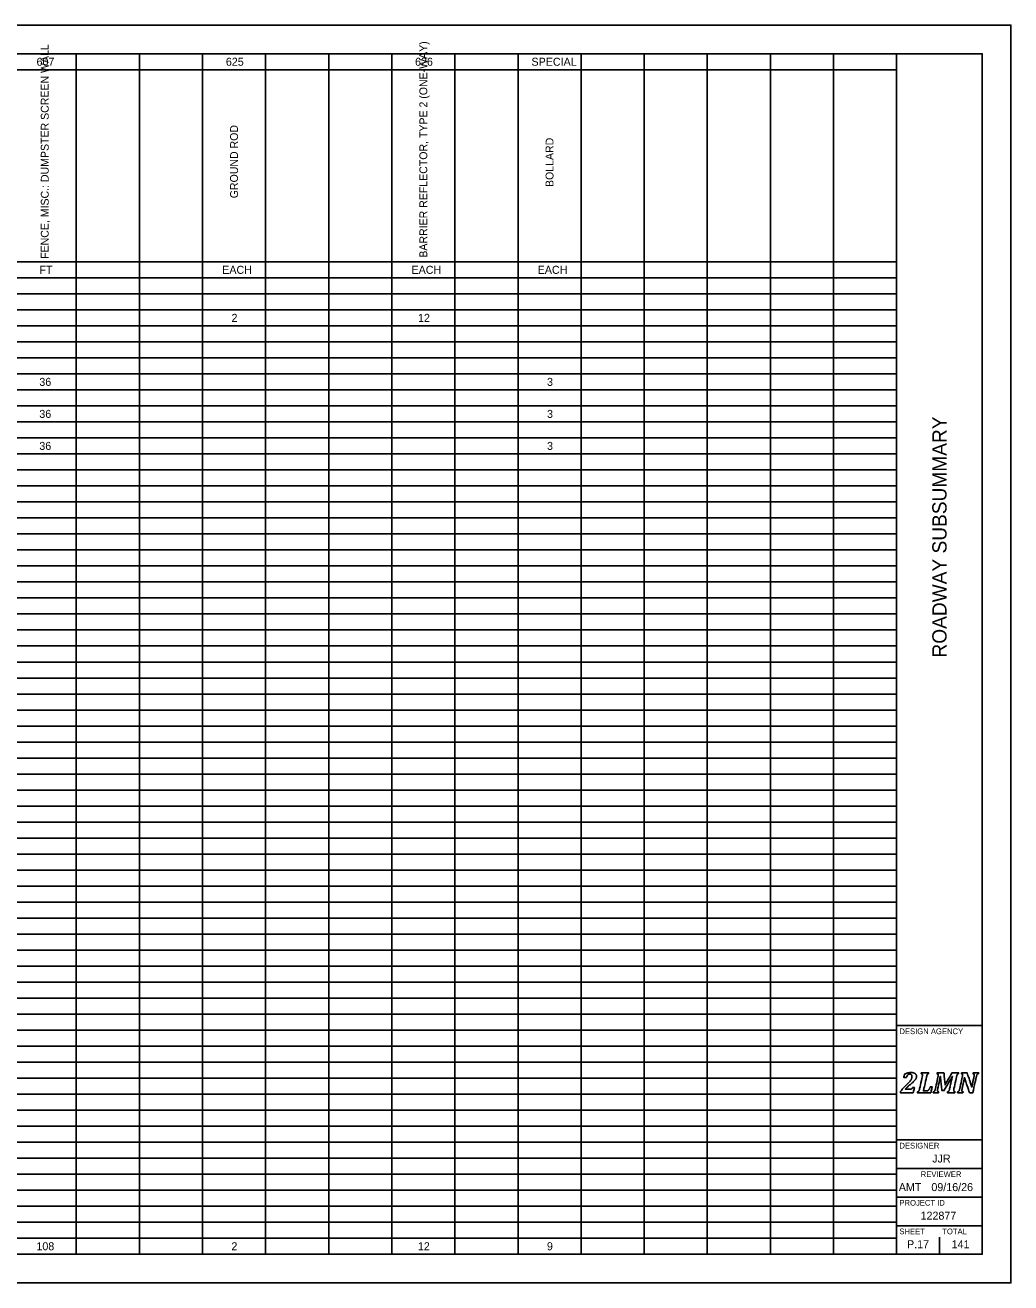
# Model space of a CAD drawing. Extents: x 0 to 34, y 0 to 22.
# Drawn here: x 16.75 to 34, y 0 to 22 of the extents above; entities that cross this region are included whole.
import ezdxf

# ---------------------------------------------------------------- set-up
doc = ezdxf.new("R2010")
doc.units = 0
for name, color, linetype in [('SH_Border', 7, 'Continuous'), ('SH_Cut_Line', 7, 'Continuous'), ('SH_Data', 7, 'Continuous'), ('SH_Text', 7, 'Continuous')]:
    doc.layers.add(name, color=color, linetype=linetype)

msp = doc.modelspace()

# ---------------------------------------------------------------- linework, layer by layer
at = {"layer": 'SH_Border'}
for p, q in [((32, 0.5), (32, 21.5)), ((32, 4.5), (33.5, 4.5)), ((32, 2.5), (33.5, 2.5)), ((32, 2), (33.5, 2)), ((32, 1.5), (33.5, 1.5)), ((32, 1), (33.5, 1))]:
    msp.add_line(p, q, dxfattribs=at)
msp.add_lwpolyline([(1.5, 21.5), (33.5, 21.5), (33.5, 0.5), (1.5, 0.5)], close=True, dxfattribs=at)
at = {"layer": 'SH_Cut_Line'}
msp.add_lwpolyline([(0, 0), (34, 0), (34, 22), (0, 22)], close=True, dxfattribs=at)
at = {"layer": 'SH_Data'}
for p, q in [((32.75, 3.5), (32.75, 3.5)), ((32.375, 0.675), (32.375, 0.675)), ((32.75, 0.5), (32.75, 0.8))]:
    msp.add_line(p, q, dxfattribs=at)
for points in [[(32.237, 3.388), (32.246, 3.388), (32.253, 3.389), (32.258, 3.39), (32.263, 3.392), (32.267, 3.394), (32.27, 3.397), (32.273, 3.401), (32.277, 3.408), (32.281, 3.417), (32.281, 3.417), (32.312, 3.417), (32.312, 3.417), (32.312, 3.417), (32.29, 3.326), (32.29, 3.326), (32.29, 3.326), (32.066, 3.326), (32.066, 3.326), (32.066, 3.326), (32.069, 3.343), (32.069, 3.343), (32.078, 3.358), (32.091, 3.375), (32.106, 3.394), (32.122, 3.412), (32.144, 3.435), (32.172, 3.462), (32.197, 3.486), (32.217, 3.506), (32.23, 3.521), (32.243, 3.537), (32.253, 3.551), (32.259, 3.566), (32.266, 3.58), (32.269, 3.595), (32.269, 3.61), (32.269, 3.622), (32.266, 3.632), (32.26, 3.64), (32.253, 3.647), (32.245, 3.65), (32.234, 3.65), (32.22, 3.65), (32.208, 3.646), (32.198, 3.636), (32.188, 3.627), (32.18, 3.613), (32.172, 3.593), (32.172, 3.593), (32.126, 3.593), (32.126, 3.593), (32.126, 3.593), (32.14, 3.654), (32.14, 3.654), (32.166, 3.663), (32.188, 3.669), (32.205, 3.673), (32.223, 3.676), (32.24, 3.678), (32.258, 3.678), (32.278, 3.678), (32.295, 3.675), (32.309, 3.669), (32.322, 3.664), (32.332, 3.656), (32.339, 3.646), (32.345, 3.637), (32.348, 3.626), (32.348, 3.613), (32.348, 3.602), (32.346, 3.591), (32.342, 3.581), (32.339, 3.571), (32.333, 3.56), (32.324, 3.549), (32.315, 3.539), (32.304, 3.526), (32.289, 3.513), (32.275, 3.499), (32.254, 3.482), (32.228, 3.46), (32.216, 3.45), (32.202, 3.438), (32.188, 3.425), (32.174, 3.412), (32.162, 3.4), (32.154, 3.391), (32.154, 3.391), (32.153, 3.388), (32.153, 3.388), (32.153, 3.388), (32.237, 3.388), (32.237, 3.388)], [(32.237, 3.388), (32.237, 3.388), (32.153, 3.388), (32.153, 3.388), (32.153, 3.388), (32.154, 3.391), (32.154, 3.391), (32.162, 3.4), (32.174, 3.412), (32.188, 3.425), (32.202, 3.438), (32.216, 3.45), (32.228, 3.46), (32.254, 3.482), (32.275, 3.499), (32.289, 3.513), (32.304, 3.526), (32.315, 3.539), (32.324, 3.549), (32.333, 3.56), (32.339, 3.571), (32.342, 3.581), (32.346, 3.591), (32.348, 3.602), (32.348, 3.613), (32.348, 3.626), (32.345, 3.637), (32.339, 3.646), (32.332, 3.656), (32.322, 3.664), (32.309, 3.669), (32.295, 3.675), (32.278, 3.678), (32.258, 3.678), (32.24, 3.678), (32.223, 3.676), (32.205, 3.673), (32.188, 3.669), (32.166, 3.663), (32.14, 3.654), (32.14, 3.654), (32.126, 3.593), (32.126, 3.593), (32.126, 3.593), (32.172, 3.593), (32.172, 3.593), (32.18, 3.613), (32.188, 3.627), (32.198, 3.636), (32.208, 3.646), (32.22, 3.65), (32.234, 3.65), (32.245, 3.65), (32.253, 3.647), (32.26, 3.64), (32.266, 3.632), (32.269, 3.622), (32.269, 3.61), (32.269, 3.595), (32.266, 3.58), (32.259, 3.566), (32.253, 3.551), (32.243, 3.537), (32.23, 3.521), (32.217, 3.506), (32.197, 3.486), (32.172, 3.462), (32.144, 3.435), (32.122, 3.412), (32.106, 3.394), (32.091, 3.375), (32.078, 3.358), (32.069, 3.343), (32.069, 3.343), (32.066, 3.326), (32.066, 3.326), (32.066, 3.326), (32.29, 3.326), (32.29, 3.326), (32.29, 3.326), (32.312, 3.417), (32.312, 3.417), (32.312, 3.417), (32.281, 3.417), (32.281, 3.417), (32.277, 3.408), (32.273, 3.401), (32.27, 3.397), (32.267, 3.394), (32.263, 3.392), (32.258, 3.39), (32.253, 3.389), (32.246, 3.388), (32.237, 3.388)], [(32.518, 3.356), (32.527, 3.356), (32.533, 3.357), (32.538, 3.358), (32.542, 3.36), (32.546, 3.362), (32.55, 3.365), (32.554, 3.368), (32.558, 3.372), (32.562, 3.377), (32.567, 3.382), (32.571, 3.388), (32.576, 3.397), (32.58, 3.405), (32.585, 3.415), (32.589, 3.427), (32.589, 3.427), (32.624, 3.427), (32.624, 3.427), (32.624, 3.427), (32.598, 3.326), (32.598, 3.326), (32.598, 3.326), (32.365, 3.326), (32.365, 3.326), (32.365, 3.326), (32.369, 3.343), (32.369, 3.343), (32.376, 3.345), (32.381, 3.348), (32.385, 3.351), (32.389, 3.355), (32.392, 3.36), (32.395, 3.366), (32.398, 3.373), (32.4, 3.382), (32.403, 3.395), (32.403, 3.395), (32.449, 3.605), (32.449, 3.605), (32.452, 3.615), (32.453, 3.625), (32.453, 3.635), (32.453, 3.642), (32.451, 3.647), (32.448, 3.651), (32.444, 3.654), (32.439, 3.656), (32.432, 3.657), (32.432, 3.657), (32.435, 3.674), (32.435, 3.674), (32.435, 3.674), (32.563, 3.674), (32.563, 3.674), (32.563, 3.674), (32.559, 3.657), (32.559, 3.657), (32.552, 3.655), (32.547, 3.652), (32.543, 3.649), (32.539, 3.645), (32.536, 3.64), (32.533, 3.634), (32.531, 3.627), (32.528, 3.618), (32.525, 3.605), (32.525, 3.605), (32.47, 3.356), (32.47, 3.356), (32.47, 3.356), (32.518, 3.356), (32.518, 3.356)], [(32.518, 3.356), (32.518, 3.356), (32.47, 3.356), (32.47, 3.356), (32.47, 3.356), (32.525, 3.605), (32.525, 3.605), (32.528, 3.618), (32.531, 3.627), (32.533, 3.634), (32.536, 3.64), (32.539, 3.645), (32.543, 3.649), (32.547, 3.652), (32.552, 3.655), (32.559, 3.657), (32.559, 3.657), (32.563, 3.674), (32.563, 3.674), (32.563, 3.674), (32.435, 3.674), (32.435, 3.674), (32.435, 3.674), (32.432, 3.657), (32.432, 3.657), (32.439, 3.656), (32.444, 3.654), (32.448, 3.651), (32.451, 3.647), (32.453, 3.642), (32.453, 3.635), (32.453, 3.625), (32.452, 3.615), (32.449, 3.605), (32.449, 3.605), (32.403, 3.395), (32.403, 3.395), (32.4, 3.382), (32.398, 3.373), (32.395, 3.366), (32.392, 3.36), (32.389, 3.355), (32.385, 3.351), (32.381, 3.348), (32.376, 3.345), (32.369, 3.343), (32.369, 3.343), (32.365, 3.326), (32.365, 3.326), (32.365, 3.326), (32.598, 3.326), (32.598, 3.326), (32.598, 3.326), (32.624, 3.427), (32.624, 3.427), (32.624, 3.427), (32.589, 3.427), (32.589, 3.427), (32.585, 3.415), (32.58, 3.405), (32.576, 3.397), (32.571, 3.388), (32.567, 3.382), (32.562, 3.377), (32.558, 3.372), (32.554, 3.368), (32.55, 3.365), (32.546, 3.362), (32.542, 3.36), (32.538, 3.358), (32.533, 3.357), (32.527, 3.356), (32.518, 3.356)], [(32.829, 3.674), (32.829, 3.674), (32.849, 3.461), (32.849, 3.461), (32.849, 3.461), (32.969, 3.674), (32.969, 3.674), (32.969, 3.674), (33.087, 3.674), (33.087, 3.674), (33.087, 3.674), (33.084, 3.657), (33.084, 3.657), (33.077, 3.655), (33.071, 3.652), (33.067, 3.649), (33.064, 3.645), (33.06, 3.64), (33.058, 3.634), (33.055, 3.627), (33.052, 3.618), (33.05, 3.605), (33.05, 3.605), (33.003, 3.395), (33.003, 3.395), (33.002, 3.39), (33.002, 3.387), (33.001, 3.384), (33.001, 3.382), (33.001, 3.379), (33, 3.376), (33, 3.373), (33, 3.369), (33, 3.365), (33, 3.358), (33.002, 3.353), (33.005, 3.349), (33.008, 3.346), (33.014, 3.344), (33.021, 3.343), (33.021, 3.343), (33.018, 3.326), (33.018, 3.326), (33.018, 3.326), (32.89, 3.326), (32.89, 3.326), (32.89, 3.326), (32.893, 3.343), (32.893, 3.343), (32.9, 3.345), (32.906, 3.348), (32.91, 3.351), (32.914, 3.355), (32.917, 3.36), (32.919, 3.366), (32.922, 3.373), (32.925, 3.382), (32.928, 3.395), (32.928, 3.395), (32.951, 3.502), (32.951, 3.502), (32.954, 3.513), (32.957, 3.529), (32.962, 3.548), (32.967, 3.568), (32.972, 3.588), (32.978, 3.609), (32.978, 3.609), (32.973, 3.609), (32.973, 3.609), (32.965, 3.594), (32.957, 3.579), (32.948, 3.563), (32.948, 3.563), (32.833, 3.364), (32.833, 3.364), (32.833, 3.364), (32.792, 3.364), (32.792, 3.364), (32.792, 3.364), (32.775, 3.518), (32.775, 3.518), (32.773, 3.537), (32.772, 3.554), (32.77, 3.569), (32.769, 3.583), (32.768, 3.597), (32.768, 3.611), (32.768, 3.611), (32.764, 3.611), (32.764, 3.611), (32.761, 3.596), (32.758, 3.578), (32.755, 3.558), (32.751, 3.538), (32.747, 3.521), (32.744, 3.507), (32.744, 3.507), (32.72, 3.395), (32.72, 3.395), (32.719, 3.39), (32.718, 3.387), (32.718, 3.384), (32.717, 3.382), (32.717, 3.379), (32.717, 3.376), (32.717, 3.373), (32.716, 3.369), (32.716, 3.365), (32.716, 3.358), (32.718, 3.353), (32.721, 3.349), (32.725, 3.346), (32.73, 3.344), (32.738, 3.343), (32.738, 3.343), (32.734, 3.326), (32.734, 3.326), (32.734, 3.326), (32.641, 3.326), (32.641, 3.326), (32.641, 3.326), (32.644, 3.343), (32.644, 3.343), (32.651, 3.345), (32.657, 3.348), (32.661, 3.351), (32.665, 3.355), (32.668, 3.36), (32.67, 3.366), (32.673, 3.373), (32.676, 3.382), (32.679, 3.395), (32.679, 3.395), (32.725, 3.605), (32.725, 3.605), (32.727, 3.615), (32.728, 3.625), (32.728, 3.635), (32.728, 3.642), (32.727, 3.647), (32.723, 3.651), (32.72, 3.654), (32.715, 3.656), (32.707, 3.657), (32.707, 3.657), (32.711, 3.674), (32.711, 3.674), (32.711, 3.674), (32.829, 3.674), (32.829, 3.674)], [(32.829, 3.674), (32.829, 3.674), (32.711, 3.674), (32.711, 3.674), (32.711, 3.674), (32.707, 3.657), (32.707, 3.657), (32.715, 3.656), (32.72, 3.654), (32.723, 3.651), (32.727, 3.647), (32.728, 3.642), (32.728, 3.635), (32.728, 3.625), (32.727, 3.615), (32.725, 3.605), (32.725, 3.605), (32.679, 3.395), (32.679, 3.395), (32.676, 3.382), (32.673, 3.373), (32.67, 3.366), (32.668, 3.36), (32.665, 3.355), (32.661, 3.351), (32.657, 3.348), (32.651, 3.345), (32.644, 3.343), (32.644, 3.343), (32.641, 3.326), (32.641, 3.326), (32.641, 3.326), (32.734, 3.326), (32.734, 3.326), (32.734, 3.326), (32.738, 3.343), (32.738, 3.343), (32.73, 3.344), (32.725, 3.346), (32.721, 3.349), (32.718, 3.353), (32.716, 3.358), (32.716, 3.365), (32.716, 3.369), (32.717, 3.373), (32.717, 3.376), (32.717, 3.379), (32.717, 3.382), (32.718, 3.384), (32.718, 3.387), (32.719, 3.39), (32.72, 3.395), (32.72, 3.395), (32.744, 3.507), (32.744, 3.507), (32.747, 3.521), (32.751, 3.538), (32.755, 3.558), (32.758, 3.578), (32.761, 3.596), (32.764, 3.611), (32.764, 3.611), (32.768, 3.611), (32.768, 3.611), (32.768, 3.597), (32.769, 3.583), (32.77, 3.569), (32.772, 3.554), (32.773, 3.537), (32.775, 3.518), (32.775, 3.518), (32.792, 3.364), (32.792, 3.364), (32.792, 3.364), (32.833, 3.364), (32.833, 3.364), (32.833, 3.364), (32.948, 3.563), (32.948, 3.563), (32.957, 3.579), (32.965, 3.594), (32.973, 3.609), (32.973, 3.609), (32.978, 3.609), (32.978, 3.609), (32.972, 3.588), (32.967, 3.568), (32.962, 3.548), (32.957, 3.529), (32.954, 3.513), (32.951, 3.502), (32.951, 3.502), (32.928, 3.395), (32.928, 3.395), (32.925, 3.382), (32.922, 3.373), (32.919, 3.366), (32.917, 3.36), (32.914, 3.355), (32.91, 3.351), (32.906, 3.348), (32.9, 3.345), (32.893, 3.343), (32.893, 3.343), (32.89, 3.326), (32.89, 3.326), (32.89, 3.326), (33.018, 3.326), (33.018, 3.326), (33.018, 3.326), (33.021, 3.343), (33.021, 3.343), (33.014, 3.344), (33.008, 3.346), (33.005, 3.349), (33.002, 3.353), (33, 3.358), (33, 3.365), (33, 3.369), (33, 3.373), (33, 3.376), (33.001, 3.379), (33.001, 3.382), (33.001, 3.384), (33.002, 3.387), (33.002, 3.39), (33.003, 3.395), (33.003, 3.395), (33.05, 3.605), (33.05, 3.605), (33.052, 3.618), (33.055, 3.627), (33.058, 3.634), (33.06, 3.64), (33.064, 3.645), (33.067, 3.649), (33.071, 3.652), (33.077, 3.655), (33.084, 3.657), (33.084, 3.657), (33.087, 3.674), (33.087, 3.674), (33.087, 3.674), (32.969, 3.674), (32.969, 3.674), (32.969, 3.674), (32.849, 3.461), (32.849, 3.461), (32.849, 3.461), (32.829, 3.674), (32.829, 3.674)], [(33.137, 3.674), (33.137, 3.674), (33.234, 3.674), (33.234, 3.674), (33.234, 3.674), (33.283, 3.53), (33.283, 3.53), (33.296, 3.49), (33.307, 3.456), (33.315, 3.426), (33.315, 3.426), (33.318, 3.426), (33.318, 3.426), (33.323, 3.455), (33.329, 3.488), (33.337, 3.523), (33.337, 3.523), (33.355, 3.605), (33.355, 3.605), (33.357, 3.615), (33.358, 3.625), (33.358, 3.635), (33.358, 3.642), (33.357, 3.647), (33.353, 3.651), (33.35, 3.654), (33.345, 3.656), (33.337, 3.657), (33.337, 3.657), (33.341, 3.674), (33.341, 3.674), (33.341, 3.674), (33.434, 3.674), (33.434, 3.674), (33.434, 3.674), (33.431, 3.657), (33.431, 3.657), (33.424, 3.655), (33.418, 3.652), (33.414, 3.649), (33.41, 3.645), (33.407, 3.64), (33.405, 3.634), (33.402, 3.627), (33.399, 3.618), (33.396, 3.605), (33.396, 3.605), (33.335, 3.326), (33.335, 3.326), (33.335, 3.326), (33.277, 3.326), (33.277, 3.326), (33.277, 3.326), (33.216, 3.504), (33.216, 3.504), (33.211, 3.518), (33.207, 3.531), (33.204, 3.543), (33.2, 3.556), (33.195, 3.571), (33.19, 3.59), (33.19, 3.59), (33.186, 3.59), (33.186, 3.59), (33.185, 3.579), (33.182, 3.563), (33.179, 3.543), (33.175, 3.523), (33.17, 3.501), (33.165, 3.478), (33.165, 3.478), (33.147, 3.395), (33.147, 3.395), (33.146, 3.39), (33.145, 3.387), (33.145, 3.384), (33.144, 3.382), (33.144, 3.379), (33.144, 3.376), (33.143, 3.373), (33.143, 3.369), (33.143, 3.365), (33.143, 3.358), (33.145, 3.353), (33.148, 3.349), (33.152, 3.346), (33.157, 3.344), (33.164, 3.343), (33.164, 3.343), (33.161, 3.326), (33.161, 3.326), (33.161, 3.326), (33.067, 3.326), (33.067, 3.326), (33.067, 3.326), (33.071, 3.343), (33.071, 3.343), (33.078, 3.345), (33.083, 3.348), (33.087, 3.351), (33.091, 3.355), (33.094, 3.36), (33.097, 3.366), (33.1, 3.373), (33.102, 3.382), (33.105, 3.395), (33.105, 3.395), (33.151, 3.605), (33.151, 3.605), (33.154, 3.615), (33.155, 3.625), (33.155, 3.635), (33.155, 3.642), (33.153, 3.647), (33.15, 3.651), (33.146, 3.654), (33.141, 3.656), (33.134, 3.657), (33.134, 3.657), (33.137, 3.674), (33.137, 3.674)], [(33.137, 3.674), (33.137, 3.674), (33.134, 3.657), (33.134, 3.657), (33.141, 3.656), (33.146, 3.654), (33.15, 3.651), (33.153, 3.647), (33.155, 3.642), (33.155, 3.635), (33.155, 3.625), (33.154, 3.615), (33.151, 3.605), (33.151, 3.605), (33.105, 3.395), (33.105, 3.395), (33.102, 3.382), (33.1, 3.373), (33.097, 3.366), (33.094, 3.36), (33.091, 3.355), (33.087, 3.351), (33.083, 3.348), (33.078, 3.345), (33.071, 3.343), (33.071, 3.343), (33.067, 3.326), (33.067, 3.326), (33.067, 3.326), (33.161, 3.326), (33.161, 3.326), (33.161, 3.326), (33.164, 3.343), (33.164, 3.343), (33.157, 3.344), (33.152, 3.346), (33.148, 3.349), (33.145, 3.353), (33.143, 3.358), (33.143, 3.365), (33.143, 3.369), (33.143, 3.373), (33.144, 3.376), (33.144, 3.379), (33.144, 3.382), (33.145, 3.384), (33.145, 3.387), (33.146, 3.39), (33.147, 3.395), (33.147, 3.395), (33.165, 3.478), (33.165, 3.478), (33.17, 3.501), (33.175, 3.523), (33.179, 3.543), (33.182, 3.563), (33.185, 3.579), (33.186, 3.59), (33.186, 3.59), (33.19, 3.59), (33.19, 3.59), (33.195, 3.571), (33.2, 3.556), (33.204, 3.543), (33.207, 3.531), (33.211, 3.518), (33.216, 3.504), (33.216, 3.504), (33.277, 3.326), (33.277, 3.326), (33.277, 3.326), (33.335, 3.326), (33.335, 3.326), (33.335, 3.326), (33.396, 3.605), (33.396, 3.605), (33.399, 3.618), (33.402, 3.627), (33.405, 3.634), (33.407, 3.64), (33.41, 3.645), (33.414, 3.649), (33.418, 3.652), (33.424, 3.655), (33.431, 3.657), (33.431, 3.657), (33.434, 3.674), (33.434, 3.674), (33.434, 3.674), (33.341, 3.674), (33.341, 3.674), (33.341, 3.674), (33.337, 3.657), (33.337, 3.657), (33.345, 3.656), (33.35, 3.654), (33.353, 3.651), (33.357, 3.647), (33.358, 3.642), (33.358, 3.635), (33.358, 3.625), (33.357, 3.615), (33.355, 3.605), (33.355, 3.605), (33.337, 3.523), (33.337, 3.523), (33.329, 3.488), (33.323, 3.455), (33.318, 3.426), (33.318, 3.426), (33.315, 3.426), (33.315, 3.426), (33.307, 3.456), (33.296, 3.49), (33.283, 3.53), (33.283, 3.53), (33.234, 3.674), (33.234, 3.674), (33.234, 3.674), (33.137, 3.674), (33.137, 3.674)]]:
    msp.add_open_spline(points, degree=3, dxfattribs=at)
at = {"layer": 'SH_Text'}
for p, q in [((1.5, 21.5), (32, 21.5)), ((17.643, 21.5), (17.643, 0.5)), ((18.748, 21.5), (18.748, 0.5)), ((19.852, 21.5), (19.852, 0.5)), ((20.956, 21.5), (20.956, 0.5)), ((22.061, 21.5), (22.061, 0.5)), ((23.165, 21.5), (23.165, 0.5)), ((24.269, 21.5), (24.269, 0.5)), ((25.374, 21.5), (25.374, 0.5)), ((26.478, 21.5), (26.478, 0.5)), ((27.583, 21.5), (27.583, 0.5)), ((28.687, 21.5), (28.687, 0.5)), ((29.791, 21.5), (29.791, 0.5)), ((30.896, 21.5), (30.896, 0.5)), ((32, 21.5), (32, 0.5)), ((9.913, 21.22), (32, 21.22)), ((9.913, 17.86), (32, 17.86)), ((1.5, 17.58), (32, 17.58)), ((1.5, 17.3), (32, 17.3)), ((1.5, 17.02), (32, 17.02)), ((1.5, 16.74), (32, 16.74)), ((1.5, 16.46), (32, 16.46)), ((1.5, 16.18), (32, 16.18)), ((1.5, 15.9), (32, 15.9)), ((1.5, 15.62), (32, 15.62)), ((1.5, 15.34), (32, 15.34)), ((1.5, 15.06), (32, 15.06)), ((1.5, 14.78), (32, 14.78)), ((1.5, 14.5), (32, 14.5)), ((1.5, 14.22), (32, 14.22)), ((1.5, 13.94), (32, 13.94)), ((1.5, 13.66), (32, 13.66)), ((1.5, 13.38), (32, 13.38)), ((1.5, 13.1), (32, 13.1)), ((1.5, 12.82), (32, 12.82)), ((1.5, 12.54), (32, 12.54)), ((1.5, 12.26), (32, 12.26)), ((1.5, 11.98), (32, 11.98)), ((1.5, 11.7), (32, 11.7)), ((1.5, 11.42), (32, 11.42)), ((1.5, 11.14), (32, 11.14)), ((1.5, 10.86), (32, 10.86)), ((1.5, 10.58), (32, 10.58)), ((1.5, 10.3), (32, 10.3)), ((1.5, 10.02), (32, 10.02)), ((1.5, 9.74), (32, 9.74)), ((1.5, 9.46), (32, 9.46)), ((1.5, 9.18), (32, 9.18)), ((1.5, 8.9), (32, 8.9)), ((1.5, 8.62), (32, 8.62)), ((1.5, 8.34), (32, 8.34)), ((1.5, 8.06), (32, 8.06)), ((1.5, 7.78), (32, 7.78)), ((1.5, 7.5), (32, 7.5)), ((1.5, 7.22), (32, 7.22)), ((1.5, 6.94), (32, 6.94)), ((1.5, 6.66), (32, 6.66)), ((1.5, 6.38), (32, 6.38)), ((1.5, 6.1), (32, 6.1)), ((1.5, 5.82), (32, 5.82)), ((1.5, 5.54), (32, 5.54)), ((1.5, 5.26), (32, 5.26)), ((1.5, 4.98), (32, 4.98)), ((1.5, 4.7), (32, 4.7)), ((1.5, 4.42), (32, 4.42)), ((1.5, 4.14), (32, 4.14)), ((1.5, 3.86), (32, 3.86)), ((1.5, 3.58), (32, 3.58)), ((1.5, 3.3), (32, 3.3)), ((1.5, 3.02), (32, 3.02)), ((1.5, 2.74), (32, 2.74)), ((1.5, 2.46), (32, 2.46)), ((1.5, 2.18), (32, 2.18)), ((1.5, 1.9), (32, 1.9)), ((1.5, 1.62), (32, 1.62)), ((1.5, 1.34), (32, 1.34)), ((1.5, 1.06), (32, 1.06)), ((1.5, 0.78), (32, 0.78)), ((1.5, 0.5), (32, 0.5))]:
    msp.add_line(p, q, dxfattribs=at)

# ---------------------------------------------------------------- texts
at = {"layer": 'SH_Data'}
msp.add_text('ROADWAY SUBSUMMARY', height=0.25, rotation=90, dxfattribs=at).set_placement((32.875, 10.938))
for s, height, p in [('DESIGN AGENCY', 0.1, (32.05, 4.35)), ('DESIGNER', 0.1, (32.05, 2.35)), ('JJR', 0.14, (32.624, 2.105)), ('REVIEWER', 0.1, (32.422, 1.85)), ('AMT', 0.14, (32.039, 1.605)), ('09/16/26', 0.14, (32.609, 1.605)), ('PROJECT ID', 0.1, (32.05, 1.35)), ('122877', 0.14, (32.42, 1.105)), ('SHEET', 0.1, (32.05, 0.85)), ('TOTAL', 0.1, (32.8, 0.85)), ('P.17', 0.14, (32.183, 0.605)), ('141', 0.14, (32.963, 0.605))]:
    msp.add_text(s, height=height, dxfattribs=at).set_placement(p)
at = {"layer": 'SH_Text'}
for s, height, p in [('FENCE, MISC.: DUMPSTER SCREEN WALL', 0.13805, (17.16, 17.912)), ('BARRIER REFLECTOR, TYPE 2 (ONE-WAY)', 0.13805, (23.786, 17.933)), ('GROUND ROD', 0.138, (20.473, 18.972)), ('BOLLARD', 0.138, (25.995, 19.169))]:
    msp.add_text(s, height=height, rotation=90, dxfattribs=at).set_placement(p)
for s, p in [('607', (16.947, 21.29)), ('625', (20.261, 21.29)), ('626', (23.572, 21.29)), ('SPECIAL', (25.61, 21.29)), ('FT', (16.999, 17.65)), ('EACH', (20.197, 17.65)), ('EACH', (23.51, 17.65)), ('EACH', (25.718, 17.65)), ('2', (20.36, 16.81)), ('12', (23.624, 16.81)), ('36', (16.996, 15.69)), ('3', (25.882, 15.69)), ('36', (16.996, 15.13)), ('3', (25.882, 15.13)), ('36', (16.996, 14.57)), ('3', (25.882, 14.57)), ('108', (16.945, 0.57)), ('2', (20.358, 0.57)), ('12', (23.622, 0.57)), ('9', (25.88, 0.57))]:
    msp.add_text(s, height=0.14, dxfattribs=at).set_placement(p)

doc.saveas('drawing.dxf')
